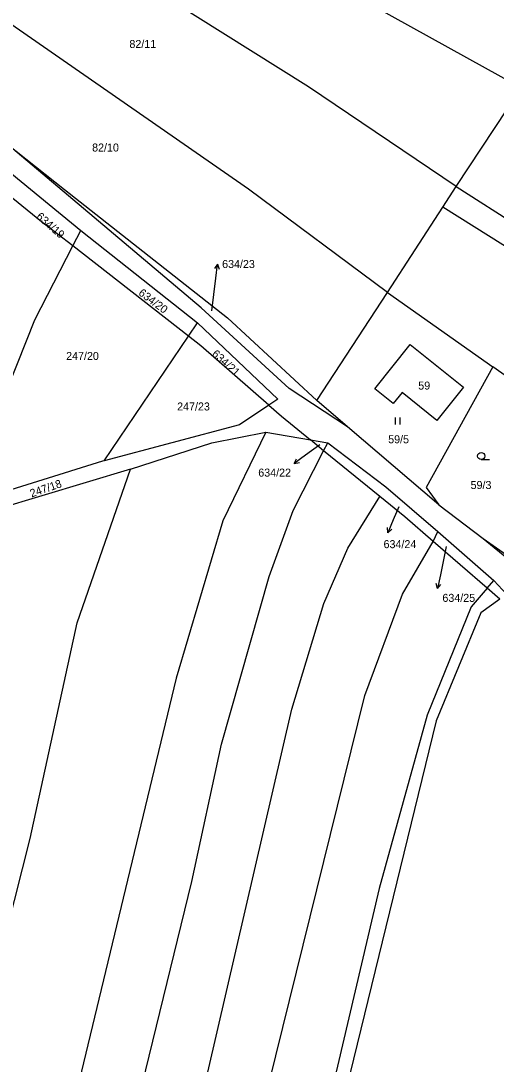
# Model space of a CAD drawing. Extents: x -746176 to -739709, y -1128407 to -1124482.
# Drawn here: x -743188.7 to -743087.7, y -1127796.2 to -1127574.6 of the extents above; entities that cross this region are included whole.
import ezdxf

# ---------------------------------------------------------------- set-up
doc = ezdxf.new("R2010")
doc.units = 0
for name, color, linetype in [('Hranice parcel', 7, 'Continuous'), ('Parcelní čísla', 7, 'Continuous'), ('Pop  PČ popisy', 7, 'Continuous'), ('Vnitřní kresba', 7, 'Continuous'), ('Značky kultur', 7, 'Continuous')]:
    doc.layers.add(name, color=color, linetype=linetype)

msp = doc.modelspace()

# ---------------------------------------------------------------- linework, layer by layer
at = {"layer": 'Hranice parcel'}
for p, q in [((-743082.43, -1127588.87), (-743239.89, -1127501.37)), ((-743096.19, -1127609.82), (-743082.43, -1127588.87)), ((-743099.02, -1127614.17), (-743096.19, -1127609.82)), ((-743096.19, -1127609.82), (-743054.68, -1127636.42)), ((-743110.84, -1127632.34), (-743099.02, -1127614.17)), ((-743057.24, -1127640.46), (-743099.02, -1127614.17)), ((-743177.68, -1127622.43), (-743175.98, -1127619.13)), ((-743175.98, -1127619.13), (-743151.19, -1127638.77)), ((-743153.1, -1127641.6), (-743177.68, -1127622.43)), ((-743125.82, -1127655.26), (-743110.84, -1127632.34)), ((-743110.84, -1127632.34), (-743088.43, -1127648.09)), ((-743153.1, -1127641.6), (-743151.19, -1127638.77)), ((-743170.99, -1127668.05), (-743153.1, -1127641.6)), ((-743062.98, -1127666.21), (-743088.43, -1127648.09)), ((-743119.31, -1127660.83), (-743125.82, -1127655.26)), ((-743136.68, -1127662.01), (-743127.19, -1127663.61)), ((-743099.92, -1127677.43), (-743119.31, -1127660.83)), ((-743124.37, -1127665.91), (-743127.19, -1127663.61)), ((-743127.19, -1127663.61), (-743123.51, -1127664.23)), ((-743124.37, -1127665.91), (-743123.51, -1127664.23)), ((-743112.44, -1127675.65), (-743124.37, -1127665.91)), ((-743165.44, -1127669.87), (-743196.8, -1127679.29)), ((-743099.92, -1127677.43), (-743090.48, -1127684.56)), ((-743101.11, -1127685.19), (-743100.14, -1127683.11)), ((-743100.14, -1127683.11), (-743088.2, -1127693.47)), ((-743089.62, -1127695.12), (-743101.11, -1127685.19)), ((-743089.62, -1127695.12), (-743088.2, -1127693.47)), ((-743088.2, -1127693.47), (-743085.48, -1127696.45)), ((-743086.91, -1127697.47), (-743089.62, -1127695.12))]:
    msp.add_line(p, q, dxfattribs=at)
for points in [[(-743096.19, -1127609.82), (-743127.6, -1127588.59), (-743246.36, -1127514.17)], [(-743110.84, -1127632.34), (-743140.32, -1127610.37), (-743254.82, -1127530.84)], [(-743201.77, -1127597.55), (-743195.41, -1127603.21), (-743175.98, -1127619.13)], [(-743119.31, -1127660.83), (-743131.7, -1127652.73), (-743150.41, -1127635.6), (-743191.76, -1127600.69)], [(-743191.76, -1127600.69), (-743179.42, -1127610.43), (-743144.82, -1127637.7), (-743125.82, -1127655.26)], [(-743177.68, -1127622.43), (-743184.29, -1127617.28), (-743197.68, -1127606.48)], [(-743200.21, -1127677.12), (-743191.34, -1127652.2), (-743185.76, -1127638.12), (-743177.68, -1127622.43)], [(-743151.19, -1127638.77), (-743134.07, -1127654.97), (-743136.01, -1127656.26)], [(-743136.01, -1127656.26), (-743150.46, -1127643.66), (-743153.1, -1127641.6)], [(-743094.66, -1127652.45), (-743100.33, -1127659.49), (-743107.72, -1127653.53), (-743109.62, -1127655.89), (-743113.52, -1127652.75), (-743105.97, -1127643.33), (-743094.66, -1127652.45)], [(-743088.43, -1127648.09), (-743102.6, -1127673.7), (-743099.92, -1127677.43)], [(-743136.01, -1127656.26), (-743142.28, -1127660.44), (-743170.99, -1127668.05)], [(-743136.01, -1127656.26), (-743133.32, -1127658.6), (-743127.19, -1127663.61)], [(-743136.68, -1127662.01), (-743145.81, -1127680.82), (-743155.72, -1127714.23), (-743186.13, -1127840.64), (-743218.63, -1127971.66), (-743232.97, -1128020.31)], [(-743165.44, -1127669.87), (-743148.15, -1127664.23), (-743136.68, -1127662.01)], [(-743123.51, -1127664.23), (-743111.14, -1127673.56), (-743100.14, -1127683.11)], [(-743211.94, -1127995.24), (-743177.21, -1127859.16), (-743152.4, -1127757.44), (-743146.1, -1127728.25), (-743135.93, -1127692.62), (-743130.84, -1127678.65), (-743124.37, -1127665.91)], [(-743170.99, -1127668.05), (-743171.32, -1127668.14), (-743200.21, -1127677.12)], [(-743237.87, -1127943.87), (-743228.87, -1127911.59), (-743204.89, -1127820), (-743186.75, -1127748.28), (-743176.72, -1127702.48), (-743165.44, -1127669.87)], [(-743183.31, -1127943.86), (-743166.85, -1127875.07), (-743131.1, -1127720.81), (-743124.32, -1127698.36), (-743119.23, -1127686.62), (-743112.44, -1127675.65)], [(-743101.11, -1127685.19), (-743107.14, -1127679.98), (-743112.44, -1127675.65)], [(-743090.48, -1127684.56), (-743071.53, -1127700.11), (-743061.74, -1127702.4), (-743058.22, -1127699.76)], [(-743159.84, -1127901.41), (-743140.31, -1127817.95), (-743115.61, -1127717.91), (-743107.65, -1127696.37), (-743101.11, -1127685.19)], [(-743089.62, -1127695.12), (-743093.02, -1127699.07), (-743102.39, -1127722.13), (-743112.61, -1127758.91), (-743139.42, -1127873.34), (-743159.84, -1127901.41)], [(-743086.91, -1127697.47), (-743090.95, -1127700.36), (-743100.45, -1127723.29), (-743120.32, -1127804.45), (-743137.57, -1127875.6)]]:
    msp.add_lwpolyline(points, dxfattribs=at)
at = {"layer": 'Pop  PČ popisy'}
for p, q in [((-743146.94, -1127626.26), (-743147.56, -1127627.19)), ((-743147.31, -1127629.24), (-743146.94, -1127626.26)), ((-743146.94, -1127626.26), (-743146.57, -1127627.32)), ((-743148.16, -1127636.21), (-743147.31, -1127629.24)), ((-743125.15, -1127664.66), (-743128.21, -1127666.85)), ((-743128.21, -1127666.85), (-743130.64, -1127668.61)), ((-743130.64, -1127668.61), (-743130.12, -1127667.62)), ((-743130.64, -1127668.61), (-743129.53, -1127668.43)), ((-743108.42, -1127677.83), (-743109.59, -1127680.57)), ((-743110.76, -1127683.33), (-743110.83, -1127682.22)), ((-743109.59, -1127680.57), (-743110.76, -1127683.33)), ((-743110.76, -1127683.33), (-743109.91, -1127682.61)), ((-743098.31, -1127686.3), (-743099.54, -1127692.26)), ((-743099.54, -1127692.26), (-743100.16, -1127695.2)), ((-743100.16, -1127695.2), (-743100.45, -1127694.11)), ((-743100.16, -1127695.2), (-743099.47, -1127694.32))]:
    msp.add_line(p, q, dxfattribs=at)
at = {"layer": 'Vnitřní kresba'}
msp.add_line((-743090.48, -1127684.56), (-743072.72, -1127697.13), dxfattribs=at)
at = {"layer": 'Značky kultur'}
for p, q in [((-743109.08, -1127660.33), (-743109.08, -1127658.83)), ((-743108.08, -1127660.33), (-743108.08, -1127658.83)), ((-743090.9, -1127667.8), (-743089.15, -1127667.8))]:
    msp.add_line(p, q, dxfattribs=at)
msp.add_circle((-743090.9, -1127667.05), 0.75, dxfattribs=at)

# ---------------------------------------------------------------- texts
at = {"layer": 'Parcelní čísla'}
for s, p in [('82/11', (-743165.64, -1127580.37)), ('82/10', (-743173.56, -1127602.36)), ('634/23', (-743145.94, -1127627.11)), ('247/20', (-743179.08, -1127646.64)), ('59', (-743104.27, -1127652.93)), ('247/23', (-743155.5, -1127657.37)), ('59/5', (-743110.66, -1127664.34)), ('634/22', (-743138.26, -1127671.42)), ('59/3', (-743093.15, -1127674.05)), ('634/24', (-743111.64, -1127686.62)), ('634/25', (-743099.14, -1127698.03))]:
    msp.add_text(s, height=1.7, dxfattribs=at).set_placement(p)
for s, rotation, p in [('634/19', 319, (-743185.57, -1127616.4)), ('634/20', 323, (-743163.86, -1127632.7)), ('634/21', 318, (-743148.25, -1127645.56)), ('247/18', 19, (-743186.43, -1127675.86))]:
    msp.add_text(s, height=1.7, rotation=rotation, dxfattribs=at).set_placement(p)

doc.saveas('drawing.dxf')
